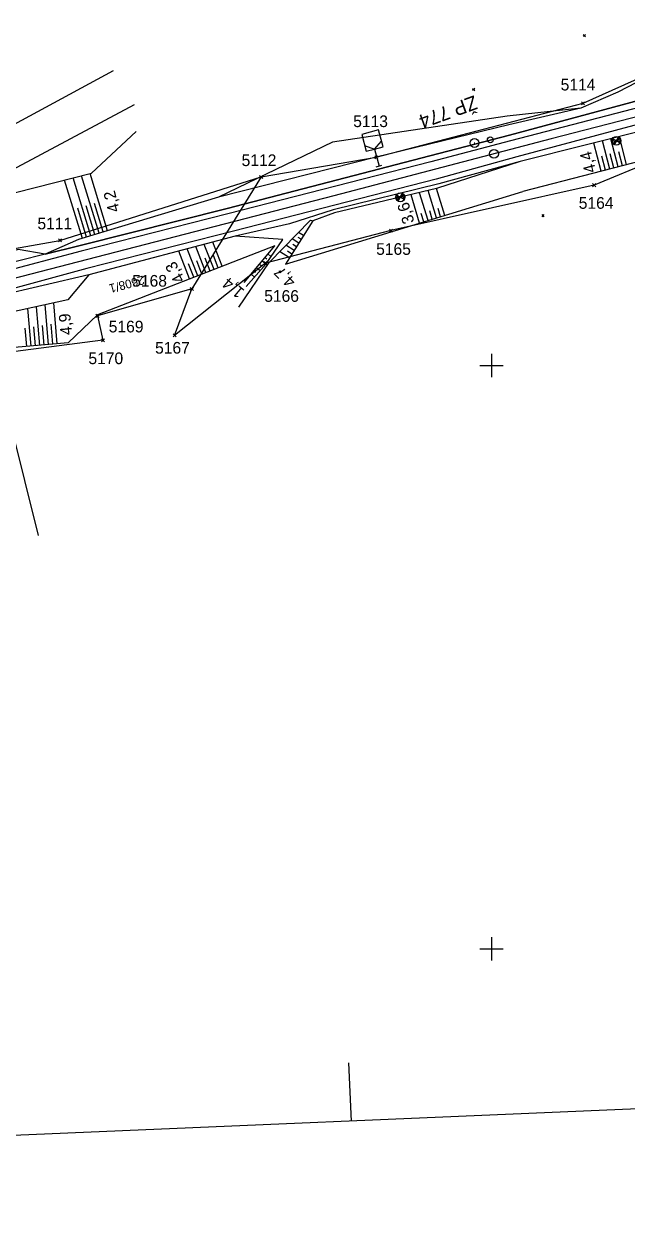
# Model space of a CAD drawing. Extents: x -806456 to -805395, y -1150847 to -1150506.
# Drawn here: x -806080.1 to -805976.8, y -1150847.3 to -1150641.5 of the extents above; entities that cross this region are included whole.
import ezdxf

# ---------------------------------------------------------------- set-up
doc = ezdxf.new("R2010")
doc.units = 0
for name, color, linetype in [('0381KM032-037P - Vrstva 1', 7, 'Continuous'), ('0381KM032-037P - Vrstva 4', 7, 'Continuous'), ('0381KM032-037P - Vrstva 48', 7, 'Continuous'), ('0381KM032-037P - Vrstva 49', 7, 'Continuous'), ('0381KM032-037P - Vrstva 51', 7, 'Continuous'), ('0381KM032-037P - Vrstva 55', 7, 'Continuous'), ('0381KM032-037P - Vrstva 57', 7, 'Continuous'), ('0381KM032-037P - Vrstva 7', 7, 'Continuous'), ('formát', 7, 'Continuous'), ('krizky_1000 - Vrstva 1', 7, 'Continuous'), ('szdc - hran DP', 7, 'Continuous'), ('szdc - szdc_cislo', 7, 'Continuous'), ('szdc - szdc_krizek', 7, 'Continuous'), ('vyt_sit - stávající', 7, 'Continuous')]:
    doc.layers.add(name, color=color, linetype=linetype)

msp = doc.modelspace()

# ---------------------------------------------------------------- linework, layer by layer
at = {"layer": '0381KM032-037P - Vrstva 1'}
for points in [[(-805955.36, -1150652.84), (-805972.27, -1150656.66), (-805989.76, -1150661.17)], [(-805989.76, -1150661.17), (-806027.03, -1150670.9), (-806064.32, -1150680.56), (-806101.67, -1150690.24), (-806138.44, -1150699.75), (-806158.28, -1150704.94), (-806163.64, -1150706.34), (-806175.38, -1150709.4), (-806186.46, -1150712.29), (-806205.2, -1150717.19), (-806213.26, -1150719.29)]]:
    msp.add_lwpolyline(points, dxfattribs=at)
at = {"layer": '0381KM032-037P - Vrstva 4'}
msp.add_line((-806068.97, -1150684.48), (-806092.67, -1150690), dxfattribs=at)
for points in [[(-805920.59, -1150645.08), (-805938.49, -1150646.69), (-805957, -1150650.24), (-805973.18, -1150654.13), (-805996.94, -1150660.52), (-806010.57, -1150664.04), (-806045.29, -1150673.07), (-806070.44, -1150679.45), (-806076.44, -1150680.94), (-806080.95, -1150682.04), (-806094.16, -1150685.34), (-806107.83, -1150689.09)], [(-805923.83, -1150646.61), (-805939.39, -1150648.49), (-805956.78, -1150651.56), (-805972.77, -1150655.27), (-805996.74, -1150661.47), (-806010.38, -1150665.11), (-806045.15, -1150673.98), (-806070.28, -1150680.43), (-806094.02, -1150686.67), (-806107.78, -1150690.05)], [(-805923.37, -1150650.9), (-805938.15, -1150652.42), (-805956.35, -1150655.74), (-805972.37, -1150659.35), (-805995.12, -1150665.03), (-806009.04, -1150668.86), (-806027.1, -1150673.31), (-806034.62, -1150675.7), (-806043.91, -1150677.85), (-806068.97, -1150684.48)], [(-805923.42, -1150649.97), (-805938.4, -1150651.47), (-805956.35, -1150654.55), (-805972.44, -1150657.98), (-805995.68, -1150664.21)], [(-805995.68, -1150664.21), (-806009.49, -1150668.04), (-806044.17, -1150677), (-806069.3, -1150683.37)], [(-806069.3, -1150683.37), (-806092.84, -1150689.77), (-806092.67, -1150690)]]:
    msp.add_lwpolyline(points, dxfattribs=at)
at = {"layer": '0381KM032-037P - Vrstva 48'}
for p, q in [((-805978.31, -1150665.95), (-805979.56, -1150661.14)), ((-805976.86, -1150665.57), (-805978.1, -1150660.78)), ((-805981.21, -1150666.7), (-805982.47, -1150661.87)), ((-805979.76, -1150666.33), (-805981.01, -1150661.51)), ((-805977.58, -1150665.76), (-805978.21, -1150663.36)), ((-805980.48, -1150666.52), (-805981.11, -1150664.1)), ((-805979.03, -1150666.14), (-805979.66, -1150663.73)), ((-806067.21, -1150677.34), (-806070.2, -1150667.47)), ((-806065.78, -1150676.91), (-806068.75, -1150667.1)), ((-806070.08, -1150678.21), (-806073.11, -1150668.21)), ((-806068.65, -1150677.78), (-806071.66, -1150667.84)), ((-806012.31, -1150675.59), (-806013.79, -1150670.73)), ((-806010.87, -1150675.15), (-806012.33, -1150670.38)), ((-806009.44, -1150674.72), (-806010.87, -1150670.03)), ((-806008, -1150674.28), (-806009.41, -1150669.68)), ((-806069.37, -1150678), (-806070.88, -1150673.01)), ((-806067.93, -1150677.56), (-806069.43, -1150672.61)), ((-806066.49, -1150677.12), (-806067.98, -1150672.21)), ((-806010.15, -1150674.93), (-806010.59, -1150673.52)), ((-806008.72, -1150674.5), (-806009.14, -1150673.1)), ((-806011.59, -1150675.37), (-806012.03, -1150673.93)), ((-806032.2, -1150677.73), (-806033.07, -1150677.19)), ((-806048.91, -1150684.08), (-806050.65, -1150679.63)), ((-806047.52, -1150683.53), (-806049.19, -1150679.24)), ((-806046.12, -1150682.99), (-806047.73, -1150678.86)), ((-806033.78, -1150680.28), (-806035.21, -1150679.39)), ((-806032.99, -1150679.01), (-806034.14, -1150678.29)), ((-806033.39, -1150679.64), (-806034.03, -1150679.24)), ((-806032.59, -1150678.37), (-806033.1, -1150678.06)), ((-806051.71, -1150685.17), (-806053.56, -1150680.4)), ((-806050.31, -1150684.62), (-806052.1, -1150680.01)), ((-806048.21, -1150683.81), (-806049.07, -1150681.62)), ((-806046.82, -1150683.26), (-806047.64, -1150681.16)), ((-806038.79, -1150681.47), (-806038.49, -1150681.71)), ((-806038.31, -1150680.89), (-806037.77, -1150681.34)), ((-806034.58, -1150681.55), (-806036.29, -1150680.49)), ((-806034.18, -1150680.92), (-806034.96, -1150680.43)), ((-806051.01, -1150684.89), (-806051.92, -1150682.55)), ((-806049.61, -1150684.35), (-806050.49, -1150682.09)), ((-806040.71, -1150683.77), (-806040.41, -1150684.02)), ((-806040.23, -1150683.19), (-806039.61, -1150683.71)), ((-806039.75, -1150682.62), (-806039.43, -1150682.88)), ((-806039.27, -1150682.04), (-806038.62, -1150682.58)), ((-806041.19, -1150684.34), (-806040.59, -1150684.84)), ((-806077.37, -1150696.56), (-806077.94, -1150689.92)), ((-806075.87, -1150696.43), (-806076.46, -1150689.59)), ((-806074.38, -1150696.3), (-806074.99, -1150689.27)), ((-806078.86, -1150696.69), (-806079.42, -1150690.24)), ((-806079.61, -1150696.76), (-806079.88, -1150693.58)), ((-806078.11, -1150696.63), (-806078.4, -1150693.35)), ((-806076.62, -1150696.5), (-806076.91, -1150693.13)), ((-806075.12, -1150696.37), (-806075.43, -1150692.9))]:
    msp.add_line(p, q, dxfattribs=at)
at = {"layer": '0381KM032-037P - Vrstva 49'}
for p, q in [((-805984.28, -1150643.25), (-805983.92, -1150643.6)), ((-805983.92, -1150643.25), (-805984.27, -1150643.6)), ((-806002.88, -1150652.52), (-806003.24, -1150652.88)), ((-806003.24, -1150652.52), (-806002.88, -1150652.88)), ((-805991.06, -1150674.14), (-805991.41, -1150674.5)), ((-805991.41, -1150674.14), (-805991.06, -1150674.5)), ((-806036.06, -1150683.77), (-806036.41, -1150684.12)), ((-806036.41, -1150683.77), (-806036.06, -1150684.12))]:
    msp.add_line(p, q, dxfattribs=at)
for points in [[(-806076.44, -1150680.94), (-806070.44, -1150679.45), (-806045.29, -1150673.07), (-806010.57, -1150664.04), (-805996.94, -1150660.52), (-805973.18, -1150654.13), (-805957, -1150650.24), (-805938.49, -1150646.69)], [(-805973.62, -1150650.67), (-805978.37, -1150653.15), (-805984.72, -1150655.91), (-805997.34, -1150657.28), (-806027.21, -1150661.72), (-806046.76, -1150671.15)], [(-805923.37, -1150650.9), (-805938.15, -1150652.42), (-805956.35, -1150655.74), (-805972.37, -1150659.35), (-805995.12, -1150665.03)], [(-805923.15, -1150654.86), (-805936.98, -1150655.81), (-805944.5, -1150657.57), (-805956.52, -1150658.37), (-805958.13, -1150658.91), (-805970.8, -1150664), (-805994.63, -1150670.19)], [(-805984.72, -1150655.91), (-805997.04, -1150658.76), (-806019.75, -1150664.3), (-806046.76, -1150671.15)], [(-806106.83, -1150681.79), (-806087.86, -1150671.94), (-806068.49, -1150667.04), (-806060.84, -1150659.9)], [(-805995.12, -1150665.03), (-806009.04, -1150668.86), (-806027.1, -1150673.31), (-806034.62, -1150675.7), (-806043.91, -1150677.85), (-806068.97, -1150684.48)], [(-805995.12, -1150665.03), (-806009.41, -1150669.68), (-806026.88, -1150673.84), (-806030.63, -1150675.21), (-806035.27, -1150682.66)], [(-806046.76, -1150671.15), (-806070.76, -1150678.42)], [(-806035.27, -1150682.66), (-806029.14, -1150680.74), (-805994.63, -1150670.19)], [(-806043.26, -1150689.98), (-806038.08, -1150682.32), (-806030.99, -1150675.07), (-806030.63, -1150675.21)], [(-806070.76, -1150678.42), (-806076.44, -1150680.94), (-806081.09, -1150680.13), (-806094.64, -1150684.2), (-806108.26, -1150688.17)], [(-806042.38, -1150685.77), (-806037.14, -1150679.5), (-806067.5, -1150691.31), (-806072.52, -1150696.14), (-806083.69, -1150697.11)], [(-806042.01, -1150686.47), (-806038.62, -1150682.58), (-806035.75, -1150678.39), (-806043.91, -1150677.85)], [(-806068.97, -1150684.48), (-806072.55, -1150688.73), (-806086.94, -1150691.89)]]:
    msp.add_lwpolyline(points, dxfattribs=at)
at = {"layer": '0381KM032-037P - Vrstva 51'}
for points in [[(-806140.16, -1150681.15), (-806120.15, -1150675.05), (-806107.44, -1150670.76), (-806090.7, -1150663.5), (-806064.75, -1150649.45)], [(-806121.48, -1150684.16), (-806105.03, -1150677.76), (-806088.01, -1150669.6), (-806061.17, -1150655.26)]]:
    msp.add_lwpolyline(points, dxfattribs=at)
at = {"layer": '0381KM032-037P - Vrstva 55'}
msp.add_line((-806039.45, -1150667.69), (-806051.33, -1150686.88), dxfattribs=at)
at = {"layer": '0381KM032-037P - Vrstva 7'}
for p, q in [((-806000.26, -1150661.33), (-806000.16, -1150661.33)), ((-806020.03, -1150662.91), (-806019.27, -1150665.81)), ((-806019.76, -1150665.94), (-806018.79, -1150665.69)), ((-806086.94, -1150691.89), (-806077.64, -1150729.17))]:
    msp.add_line(p, q, dxfattribs=at)
for points in [[(-806020.03, -1150662.91), (-806018.58, -1150662.53), (-806019.34, -1150659.63), (-806022.24, -1150660.39), (-806021.48, -1150663.29), (-806020.03, -1150662.91)], [(-806021.74, -1150662.32), (-806020.03, -1150662.91), (-806018.83, -1150661.56)]]:
    msp.add_lwpolyline(points, dxfattribs=at)
for centre, radius in [((-806000.21, -1150661.33), 0.5), ((-805999.58, -1150663.73), 0.75)]:
    msp.add_circle(centre, radius, dxfattribs=at)
at = {"layer": 'formát'}
for p, q in [((-806024.47, -1150819.52), (-806024.04, -1150829.52)), ((-805814.23, -1150820.61), (-806443.66, -1150847.33))]:
    msp.add_line(p, q, dxfattribs=at)
at = {"layer": 'krizky_1000 - Vrstva 1'}
for points in [[(-806000, -1150698), (-806000, -1150702)], [(-806002, -1150700), (-805998, -1150700)], [(-806000, -1150798), (-806000, -1150802)], [(-806002, -1150800), (-805998, -1150800)]]:
    msp.add_lwpolyline(points, dxfattribs=at)
at = {"layer": 'szdc - hran DP'}
for p, q in [((-805984.31, -1150655.05), (-805954.21, -1150641.47)), ((-806019.74, -1150664.32), (-805984.31, -1150655.05)), ((-805958.14, -1150658.97), (-805982.42, -1150669.1)), ((-806039.45, -1150667.69), (-806019.74, -1150664.32)), ((-806073.91, -1150678.57), (-806039.45, -1150667.69)), ((-805982.42, -1150669.1), (-806017.22, -1150676.88)), ((-806017.22, -1150676.88), (-806038.72, -1150682.46)), ((-806107.35, -1150684.54), (-806073.91, -1150678.57)), ((-806038.72, -1150682.46), (-806054.27, -1150694.84)), ((-806051.33, -1150686.88), (-806067.49, -1150691.49)), ((-806054.27, -1150694.84), (-806051.33, -1150686.88)), ((-806067.49, -1150691.49), (-806066.55, -1150695.68)), ((-806066.55, -1150695.68), (-806092.7, -1150699.08))]:
    msp.add_line(p, q, dxfattribs=at)
at = {"layer": 'szdc - szdc_krizek'}
for p, q in [((-805984.05, -1150655.31), (-805984.58, -1150654.78)), ((-805984.58, -1150655.31), (-805984.05, -1150654.78)), ((-806019.47, -1150664.58), (-806020.01, -1150664.05)), ((-806020.01, -1150664.58), (-806019.47, -1150664.05)), ((-806039.19, -1150667.96), (-806039.72, -1150667.43)), ((-806039.72, -1150667.96), (-806039.19, -1150667.43)), ((-805982.16, -1150669.36), (-805982.69, -1150668.83)), ((-805982.69, -1150669.36), (-805982.16, -1150668.83)), ((-806016.96, -1150677.15), (-806017.49, -1150676.61)), ((-806017.49, -1150677.15), (-806016.96, -1150676.61)), ((-806073.65, -1150678.83), (-806074.18, -1150678.3)), ((-806074.18, -1150678.83), (-806073.65, -1150678.3)), ((-806038.46, -1150682.73), (-806038.99, -1150682.2)), ((-806038.99, -1150682.73), (-806038.46, -1150682.2)), ((-806051.07, -1150687.15), (-806051.6, -1150686.61)), ((-806051.6, -1150687.15), (-806051.07, -1150686.61)), ((-806067.22, -1150691.76), (-806067.76, -1150691.23)), ((-806067.76, -1150691.76), (-806067.22, -1150691.23)), ((-806066.29, -1150695.95), (-806066.82, -1150695.42)), ((-806066.82, -1150695.95), (-806066.29, -1150695.42)), ((-806054.01, -1150695.1), (-806054.54, -1150694.57)), ((-806054.54, -1150695.1), (-806054.01, -1150694.57))]:
    msp.add_line(p, q, dxfattribs=at)
at = {"layer": 'vyt_sit - stávající'}
for p, q in [((-805979.05, -1150661.23), (-805979.34, -1150661.72)), ((-805979.28, -1150661.1), (-805978.61, -1150661.49)), ((-805978.61, -1150661.49), (-805978.22, -1150660.83)), ((-805978.07, -1150660.95), (-805978.44, -1150661.58)), ((-805977.89, -1150661.24), (-805978.19, -1150661.74)), ((-806002.97, -1150661.86), (-806002.87, -1150661.86)), ((-805978.79, -1150661.38), (-805979.17, -1150662.01)), ((-805978.61, -1150661.49), (-805979, -1150662.15)), ((-805977.96, -1150661.87), (-805978.61, -1150661.49)), ((-806016.06, -1150670.9), (-806016.35, -1150671.39)), ((-806016.29, -1150670.77), (-806015.62, -1150671.16)), ((-806015.8, -1150671.06), (-806016.17, -1150671.69)), ((-806015.62, -1150671.16), (-806016.01, -1150671.82)), ((-806015.62, -1150671.16), (-806015.24, -1150670.5)), ((-806014.97, -1150671.54), (-806015.62, -1150671.16)), ((-806015.08, -1150670.62), (-806015.45, -1150671.26)), ((-806014.9, -1150670.91), (-806015.2, -1150671.41))]:
    msp.add_line(p, q, dxfattribs=at)
for centre, radius in [((-806002.92, -1150661.86), 0.756), ((-805978.61, -1150661.49), 0.764), ((-806015.62, -1150671.16), 0.764)]:
    msp.add_circle(centre, radius, dxfattribs=at)
for centre, radius, start, end in [((-805978.61, -1150661.49), 0.765, 149.6712, 239.5647), ((-805978.61, -1150661.49), 0.764, 328.9824, 59.3004), ((-806015.62, -1150671.16), 0.765, 149.8433, 239.7368), ((-806015.62, -1150671.16), 0.764, 329.1545, 59.4725)]:
    msp.add_arc(centre, radius, start, end, dxfattribs=at)

# ---------------------------------------------------------------- texts
at = {"layer": '0381KM032-037P - Vrstva 48'}
for s, rotation, p in [('4,4', 104.5589, (-805982.06, -1150666.72)), ('4,2', 104.1997, (-806063.65, -1150673.47)), ('3,6', 106.9987, (-806013.19, -1150675.4)), ('4,3', 119.1846, (-806052.44, -1150685.23)), ('4,7', 134.6698, (-806033.39, -1150685.47)), ('1,4', 140.1468, (-806042.18, -1150687.14)), ('4,9', 94.9542, (-806071.83, -1150694.71))]:
    msp.add_text(s, height=2, rotation=rotation, dxfattribs=at).set_placement(p)
at = {"layer": '0381KM032-037P - Vrstva 57'}
msp.add_text('2608/1', height=1.5, rotation=194.7572, dxfattribs=at).set_placement((-806059.69, -1150684.58))
at = {"layer": 'szdc - szdc_cislo'}
for s, p in [('5114', (-805988.16, -1150652.86)), ('5113', (-806023.69, -1150659.14)), ('5112', (-806042.8, -1150665.82)), ('5164', (-805985.06, -1150673.14)), ('5111', (-806077.77, -1150676.66)), ('5165', (-806019.76, -1150681.04)), ('5168', (-806061.54, -1150686.49)), ('5166', (-806038.93, -1150689.09)), ('5169', (-806065.56, -1150694.33)), ('5167', (-806057.62, -1150697.97)), ('5170', (-806069.04, -1150699.77))]:
    msp.add_text(s, height=2, dxfattribs=at).set_placement(p)
at = {"layer": 'vyt_sit - stávající'}
msp.add_text('ŽP 774', height=2.4, rotation=200, dxfattribs=at).set_placement((-806002.96, -1150653.66))

doc.saveas('drawing.dxf')
